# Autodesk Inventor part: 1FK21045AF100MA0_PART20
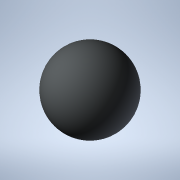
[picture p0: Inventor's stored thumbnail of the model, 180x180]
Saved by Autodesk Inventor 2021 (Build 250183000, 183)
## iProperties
Created: 2025-04
Part Number: 1FK21045AF100MA0_PART20
Material: Generic
Catalog Web Link: www.3dfindit.com
Description: -Servo synchronous motor
Document SubType Name: Modeling
Designer: psAdmin
Mass: 0.137258 g
Surface Area: 1.2868 cm^2
Volume: 0.137258 cm^3
Density: 1 g/cm^3
Appearance: PSOLRGB-212-217-219
Category: PARTsolutions
Title: 1FK21045AF100MA0_PART20
Author: Cadenas PARTsolutions
Comments: Servo synchronous motor
Sending System: PARTsolutions
Preprocessor: ST-DEVELOPER v19.3
PSOL_IDENT_0: {$CADENAS_DATA/23d-libs/siemens_ag/_cat_/52/6b/1fk21045af100ma0.prj},216 {VTYP=3D},{NB=1FK21045AF100
PSOL_IDENT_1: MA0_PART20},{LINA=1FK21045AF100MA0_PART20},{NN=1FK21045AF100MA0_PART20},{NOPRJ=TRUE},{DATE=19.08.202
PSOL_IDENT_2: 5 14:00:38},{GEOMDATE=30.07.2025 02:01:45},{VERSION=},{LINEID=10},{WBVAR=},{WBNUMERIC=}  {NB=1FK2104
PSOL_IDENT_3: 5AF100MA0_PART20},{LINA=1FK21045AF100MA0_PART20},{KT=DUMMY},{PREVIEW=../../../_pool_/cb/72/p_d211_xx
PSOL_IDENT_4: _00434j.png},{DESCSHORT=SIMOTICS S-1FK2 HD, SINAMICS S210 3AC 400V-480V, 2.4 Nm, 3000 rpm},{DESCLONG=
PSOL_IDENT_5: SIMOTICS S-1FK2 HD servo motor M0=2.4 Nm; PN = 0.75 kW at nN=3000 rpm (380-480 V); PN = 0.375 kW at
PSOL_IDENT_6: nN=1500 rpm (200-240 V); with holding brake; degree of protection IP64; cylindrical shaft D19x40mm;
PSOL_IDENT_7: absolute encoder 22-bit + 12-bit multiturn (encoder AM22DQC); with OCC interface; plug size M17, rot
PSOL_IDENT_8: atable; SIMOTICS S-1FK2 servomotorfor a wide range of uses in industrial environments. SIMOTICS S‑1F
PSOL_IDENT_9: K2 servomotors are compact synchronous motors with a high dynamic performance that set themselves ap
PSOL_IDENT_10: art as a result of their high power density, degree of protection and overload capability. The motor
PSOL_IDENT_11: s are available in two variants: as High Dynamic variant (highest dynamic performance as a result of
PSOL_IDENT_12: the low intrinsic moment of inertia for applications demanding a high dynamic performance with low
PSOL_IDENT_13: moved masses) - and as Compact variant (precise and stable closed-loop control for medium up to larg
PSOL_IDENT_14: e moved masses as a result of a medium intrinsic moment of inertia). SIMOTICSS‑1FK2 servomotors full
PSOL_IDENT_15: y exploit their strengths in a system with the SINAMICSS210 frequency converter and simple connectio
PSOL_IDENT_16: n using the one cable connection (OCC). Advantages include the short control and positioning times,
PSOL_IDENT_17: fast and precise correction of disturbing quantities as well as stable control with a high dynamic p
PSOL_IDENT_18: erformance. The servo motors can be configured to address a wide range of requirements. For example
PSOL_IDENT_19: with and without holding brake, IP64 or IP65 degree of protection, singleturn or multiturn absolute
PSOL_IDENT_20: encoders - to name just a few. Further, the servomotors are available in different shaft heights ext
PSOL_IDENT_21: ending from 20 to 100. A shaft sealing ring is available to achieve an IP65 degree of protection and
PSOL_IDENT_22: for subsequent mounting at the motor or as spare part. SIMOTICS - the optimum motor for each and ev
PSOL_IDENT_23: ery motion control application.},{INTNO=804766906411},{SUPPLIERALTNO=1FK2104-5AF10-0MA0},{MANUID=1FK
PSOL_IDENT_24: 21045AF100MA0},{MANUNAME=Siemens},{MANUTYPEDESC=Synchronous motor 1FK2-HD 2.4 NM},{AAU732=SIMOTICS},
PSOL_IDENT_25: {AAO057=S-1FK2},{AAU734=SIMOTICS S-1FK2 HD servo motor M0=2.4 Nm; PN = 0.75 kW at nN=3000 rpm (380-4
PSOL_IDENT_26: 80 V); PN = 0.375 kW at nN=1500 rpm (200-240 V); with holding brake; degree of protection IP64; cyli
PSOL_IDENT_27: ndrical shaft D19x40mm; absolute encoder 22-bit + 12-bit multiturn (encoder AM22DQC); with OCC inter
PSOL_IDENT_28: face; plug size M17, rotatable;},{AAW338=Synchronous motor 1FK2-HD 2.4 NM},{AAO742=SIMOTICS},{AAO663=
PSOL_IDENT_29: 4042948693070},{NOCUPEROU=1},{PRICEQUANTITY=1},{QUANTITYMIN=1},{QUANTITYINT=1},{CTN=85015100},{COO=D
PSOL_IDENT_30: E},{AAO676=1FK2104-5AF10-0MA0},{AAO677=Siemens AG},{ORDERUNIT=C62},{CONTENTUNIT=C62}
NB: 1FK21045AF100MA0_PART20
NT: Servo synchronous motor
NBSYN: $MANUID._PART20
LINA: 1FK21045AF100MA0_PART20
CATALOG: SIEMENS
PREVIEW: ../../../_pool_/cb/72/p_d211_xx_00434j.png
DESCSHORT: SIMOTICS S-1FK2 HD, SINAMICS S210 3AC 400V-480V, 2.4 Nm, 3000 rpm
DESCLONG: SIMOTICS S-1FK2 HD servo motor M0=2.4 Nm; PN = 0.75 kW at nN=3000 rpm (380-480 V); PN = 0.375 kW at nN=1500 rpm (200-240 V); with holding brake; degree of prote
INTNO: 804766906411
SUPPLIERALTNO: 1FK2104-5AF10-0MA0
MANUID: 1FK21045AF100MA0
MANUNAME: Siemens
MANUTYPEDESC: Synchronous motor 1FK2-HD 2.4 NM
AAU732: SIMOTICS
AAO057: S-1FK2
AAU734: SIMOTICS S-1FK2 HD servo motor M0=2.4 Nm; PN = 0.75 kW at nN=3000 rpm (380-480 V); PN = 0.375 kW at nN=1500 rpm (200-240 V); with holding brake; degree of prote
AAW338: Synchronous motor 1FK2-HD 2.4 NM
AAO742: SIMOTICS
AAO663: 4042948693070.0
NOCUPEROU: 1
PRICEQUANTITY: 1
QUANTITYMIN: 1
QUANTITYINT: 1
CTN: 85015100
COO: DE
ARTICLENO: 1FK21045AF100MA0_PART20
BOMINFO: 1FK21045AF100MA0_PART20
CREATOR: CADENAS GmbH
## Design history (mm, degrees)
feature "2025_04_17_15_34_52_0317"
body "Solid1"
